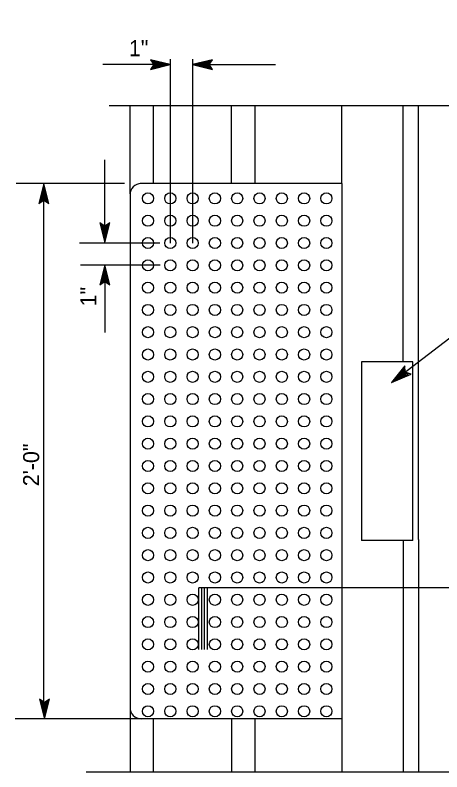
# Model space of a CAD drawing. Extents: x 6710407 to 6714861, y 1868090 to 1871317.
# Drawn here: x 6712493.6 to 6712653, y 1869454.7 to 1869737.5 of the extents above; entities that cross this region are included whole.
import ezdxf

# ---------------------------------------------------------------- set-up
doc = ezdxf.new("R2010")
doc.units = 0
for name, color, linetype in [('G-MARK', 7, 'Continuous'), ('G-TEXT', 7, 'Continuous'), ('Nongeo Data(60)', 7, 'Continuous')]:
    doc.layers.add(name, color=color, linetype=linetype)

msp = doc.modelspace()

# ---------------------------------------------------------------- linework, layer by layer
at = {"layer": 'G-MARK'}
for p, q in [((6712634.16, 1869600.18), (6712812.33, 1869737.52)), ((6712551.55, 1869652.35), (6712551.55, 1869721.02)), ((6712559.89, 1869652.35), (6712559.89, 1869721.02)), ((6712551.49, 1869719.01), (6712526.31, 1869719.01)), ((6712559.82, 1869719.01), (6712590.83, 1869719.01)), ((6712662.99, 1869703.6), (6712528.65, 1869703.6)), ((6712527.08, 1869652.44), (6712527.08, 1869683.45)), ((6712534.39, 1869674.55), (6712493.89, 1869674.55)), ((6712504.23, 1869479.61), (6712504.23, 1869674.55)), ((6712547.67, 1869652.35), (6712517.54, 1869652.35)), ((6712547.77, 1869644.02), (6712517.94, 1869644.02)), ((6712527.08, 1869644.11), (6712527.08, 1869618.94)), ((6712578.2, 1869474.55), (6712493.56, 1869474.55)), ((6712520.13, 1869454.7), (6712662.61, 1869454.7))]:
    msp.add_line(p, q, dxfattribs=at)
at = {"layer": 'G-TEXT'}
for points in [[(6712551.49, 1869719.01), (6712544.08, 1869720.86), (6712545.31, 1869719.01), (6712544.08, 1869717.15), (6712551.49, 1869719.01)], [(6712551.49, 1869719.01), (6712544.08, 1869720.86), (6712545.31, 1869719.01), (6712544.08, 1869717.15), (6712551.49, 1869719.01)], [(6712550.17, 1869719.01), (6712544.8, 1869720.35), (6712545.7, 1869719.01), (6712544.8, 1869717.66), (6712550.17, 1869719.01)], [(6712550.17, 1869719.01), (6712544.8, 1869720.35), (6712545.7, 1869719.01), (6712544.8, 1869717.66), (6712550.17, 1869719.01)], [(6712549.07, 1869719.01), (6712545.41, 1869719.93), (6712546.02, 1869719.01), (6712545.41, 1869718.09), (6712549.07, 1869719.01)], [(6712549.07, 1869719.01), (6712545.41, 1869719.93), (6712546.02, 1869719.01), (6712545.41, 1869718.09), (6712549.07, 1869719.01)], [(6712559.82, 1869719.01), (6712567.23, 1869717.15), (6712566, 1869719.01), (6712567.23, 1869720.86), (6712559.82, 1869719.01)], [(6712561.14, 1869719.01), (6712566.51, 1869717.66), (6712565.61, 1869719.01), (6712566.51, 1869720.35), (6712561.14, 1869719.01)], [(6712562.24, 1869719.01), (6712565.9, 1869718.09), (6712565.29, 1869719.01), (6712565.9, 1869719.93), (6712562.24, 1869719.01)], [(6712548.16, 1869719.01), (6712545.91, 1869719.58), (6712546.28, 1869719.01), (6712545.91, 1869718.44), (6712548.16, 1869719.01)], [(6712548.16, 1869719.01), (6712545.91, 1869719.58), (6712546.28, 1869719.01), (6712545.91, 1869718.44), (6712548.16, 1869719.01)], [(6712548.1, 1869718.78), (6712546.44, 1869719.19), (6712546.57, 1869719.01), (6712546.44, 1869718.82), (6712548.1, 1869719.24)], [(6712548.1, 1869718.78), (6712546.44, 1869719.19), (6712546.57, 1869719.01), (6712546.44, 1869718.82), (6712548.1, 1869719.24)], [(6712563.15, 1869719.01), (6712565.4, 1869718.44), (6712565.03, 1869719.01), (6712565.4, 1869719.58), (6712563.15, 1869719.01)], [(6712563.21, 1869719.24), (6712564.87, 1869718.82), (6712564.74, 1869719.01), (6712564.87, 1869719.19), (6712563.21, 1869718.78)], [(6712504.3, 1869674.55), (6712502.44, 1869667.15), (6712504.3, 1869668.38), (6712506.15, 1869667.15), (6712504.3, 1869674.55)], [(6712504.3, 1869674.55), (6712502.44, 1869667.15), (6712504.3, 1869668.38), (6712506.15, 1869667.15), (6712504.3, 1869674.55)], [(6712504.3, 1869673.24), (6712502.95, 1869667.87), (6712504.3, 1869668.76), (6712505.64, 1869667.87), (6712504.3, 1869673.24)], [(6712504.3, 1869673.24), (6712502.95, 1869667.87), (6712504.3, 1869668.76), (6712505.64, 1869667.87), (6712504.3, 1869673.24)], [(6712504.3, 1869672.14), (6712503.38, 1869668.48), (6712504.3, 1869669.09), (6712505.22, 1869668.48), (6712504.3, 1869672.14)], [(6712504.3, 1869672.14), (6712503.38, 1869668.48), (6712504.3, 1869669.09), (6712505.22, 1869668.48), (6712504.3, 1869672.14)], [(6712504.3, 1869671.23), (6712503.73, 1869668.98), (6712504.3, 1869669.35), (6712504.87, 1869668.98), (6712504.3, 1869671.23)], [(6712504.3, 1869671.23), (6712503.73, 1869668.98), (6712504.3, 1869669.35), (6712504.87, 1869668.98), (6712504.3, 1869671.23)], [(6712504.53, 1869671.17), (6712504.11, 1869669.51), (6712504.3, 1869669.63), (6712504.49, 1869669.51), (6712504.07, 1869671.17)], [(6712504.53, 1869671.17), (6712504.11, 1869669.51), (6712504.3, 1869669.63), (6712504.49, 1869669.51), (6712504.07, 1869671.17)], [(6712527.08, 1869652.44), (6712528.94, 1869659.85), (6712527.08, 1869658.62), (6712525.23, 1869659.85), (6712527.08, 1869652.44)], [(6712527.08, 1869653.76), (6712528.43, 1869659.13), (6712527.08, 1869658.23), (6712525.74, 1869659.13), (6712527.08, 1869653.76)], [(6712527.08, 1869654.86), (6712528, 1869658.52), (6712527.08, 1869657.91), (6712526.16, 1869658.52), (6712527.08, 1869654.86)], [(6712527.08, 1869655.77), (6712527.65, 1869658.02), (6712527.08, 1869657.65), (6712526.51, 1869658.02), (6712527.08, 1869655.77)], [(6712526.85, 1869655.83), (6712527.27, 1869657.49), (6712527.08, 1869657.37), (6712526.9, 1869657.49), (6712527.31, 1869655.83)], [(6712527.08, 1869644.11), (6712525.23, 1869636.7), (6712527.08, 1869637.93), (6712528.94, 1869636.7), (6712527.08, 1869644.11)], [(6712527.08, 1869644.11), (6712525.23, 1869636.7), (6712527.08, 1869637.93), (6712528.94, 1869636.7), (6712527.08, 1869644.11)], [(6712527.08, 1869642.8), (6712525.74, 1869637.43), (6712527.08, 1869638.32), (6712528.43, 1869637.43), (6712527.08, 1869642.8)], [(6712527.08, 1869642.8), (6712525.74, 1869637.43), (6712527.08, 1869638.32), (6712528.43, 1869637.43), (6712527.08, 1869642.8)], [(6712527.08, 1869641.69), (6712526.16, 1869638.04), (6712527.08, 1869638.65), (6712528, 1869638.04), (6712527.08, 1869641.69)], [(6712527.08, 1869641.69), (6712526.16, 1869638.04), (6712527.08, 1869638.65), (6712528, 1869638.04), (6712527.08, 1869641.69)], [(6712527.08, 1869640.78), (6712526.51, 1869638.53), (6712527.08, 1869638.9), (6712527.65, 1869638.53), (6712527.08, 1869640.78)], [(6712527.08, 1869640.78), (6712526.51, 1869638.53), (6712527.08, 1869638.9), (6712527.65, 1869638.53), (6712527.08, 1869640.78)], [(6712527.31, 1869640.73), (6712526.9, 1869639.07), (6712527.08, 1869639.19), (6712527.27, 1869639.07), (6712526.85, 1869640.73)], [(6712527.31, 1869640.73), (6712526.9, 1869639.07), (6712527.08, 1869639.19), (6712527.27, 1869639.07), (6712526.85, 1869640.73)], [(6712634.16, 1869600.18), (6712641.45, 1869603.36), (6712639.26, 1869604.11), (6712639.09, 1869606.42), (6712634.16, 1869600.18)], [(6712634.16, 1869600.18), (6712641.45, 1869603.36), (6712639.26, 1869604.11), (6712639.09, 1869606.42), (6712634.16, 1869600.18)], [(6712635.24, 1869601.02), (6712640.53, 1869603.33), (6712638.94, 1869603.87), (6712638.82, 1869605.54), (6712635.24, 1869601.02)], [(6712635.24, 1869601.02), (6712640.53, 1869603.33), (6712638.94, 1869603.87), (6712638.82, 1869605.54), (6712635.24, 1869601.02)], [(6712636.15, 1869601.72), (6712639.76, 1869603.29), (6712638.67, 1869603.66), (6712638.59, 1869604.81), (6712636.15, 1869601.72)], [(6712636.15, 1869601.72), (6712639.76, 1869603.29), (6712638.67, 1869603.66), (6712638.59, 1869604.81), (6712636.15, 1869601.72)], [(6712636.9, 1869602.3), (6712639.12, 1869603.26), (6712638.45, 1869603.49), (6712638.4, 1869604.2), (6712636.9, 1869602.3)], [(6712636.9, 1869602.3), (6712639.12, 1869603.26), (6712638.45, 1869603.49), (6712638.4, 1869604.2), (6712636.9, 1869602.3)], [(6712636.81, 1869602.53), (6712638.44, 1869603.24), (6712638.22, 1869603.31), (6712638.2, 1869603.55), (6712637.1, 1869602.15)], [(6712636.81, 1869602.53), (6712638.44, 1869603.24), (6712638.22, 1869603.31), (6712638.2, 1869603.55), (6712637.1, 1869602.15)], [(6712504.51, 1869474.49), (6712506.37, 1869481.9), (6712504.51, 1869480.67), (6712502.66, 1869481.9), (6712504.51, 1869474.49)], [(6712504.51, 1869475.81), (6712505.86, 1869481.18), (6712504.51, 1869480.28), (6712503.17, 1869481.18), (6712504.51, 1869475.81)], [(6712504.51, 1869476.91), (6712505.43, 1869480.57), (6712504.51, 1869479.96), (6712503.59, 1869480.57), (6712504.51, 1869476.91)], [(6712504.51, 1869477.82), (6712505.08, 1869480.07), (6712504.51, 1869479.7), (6712503.94, 1869480.07), (6712504.51, 1869477.82)], [(6712504.28, 1869477.88), (6712504.7, 1869479.54), (6712504.51, 1869479.42), (6712504.32, 1869479.54), (6712504.74, 1869477.88)]]:
    msp.add_lwpolyline(points, dxfattribs=at)
at = {"layer": 'Nongeo Data(60)'}
for p, q in [((6712536.48, 1869670.68), (6712536.48, 1869703.6)), ((6712545.3, 1869674.55), (6712545.3, 1869703.6)), ((6712574.41, 1869674.55), (6712574.41, 1869703.6)), ((6712583.23, 1869674.55), (6712583.23, 1869703.6)), ((6712615.65, 1869674.55), (6712615.65, 1869703.6)), ((6712638.51, 1869607.89), (6712638.51, 1869703.6)), ((6712644.18, 1869541.57), (6712644.18, 1869703.6)), ((6712615.65, 1869674.55), (6712540.27, 1869674.55)), ((6712615.65, 1869674.55), (6712615.65, 1869454.7)), ((6712536.48, 1869670.68), (6712536.48, 1869478.55)), ((6712622.92, 1869607.89), (6712622.92, 1869541.22)), ((6712642.15, 1869607.89), (6712622.92, 1869607.89)), ((6712642.15, 1869541.22), (6712642.15, 1869607.89)), ((6712644.18, 1869541.57), (6712644.18, 1869454.7)), ((6712642.15, 1869541.22), (6712622.92, 1869541.22)), ((6712638.51, 1869541.22), (6712638.51, 1869454.7)), ((6712792.35, 1869523.51), (6712562.23, 1869523.51)), ((6712562.23, 1869500.43), (6712562.23, 1869523.51)), ((6712563.28, 1869500.43), (6712563.28, 1869523.37)), ((6712564.34, 1869500.43), (6712564.34, 1869523.37)), ((6712565.4, 1869500.43), (6712565.4, 1869523.37)), ((6712536.48, 1869478.55), (6712536.48, 1869454.7)), ((6712615.65, 1869474.55), (6712540.65, 1869474.55)), ((6712545.3, 1869454.7), (6712545.3, 1869474.55)), ((6712574.41, 1869474.55), (6712574.41, 1869454.7)), ((6712583.23, 1869454.7), (6712583.23, 1869474.55))]:
    msp.add_line(p, q, dxfattribs=at)
for centre in [(6712543.17, 1869669.02), (6712551.5, 1869669.02), (6712559.84, 1869669.02), (6712568.17, 1869669.02), (6712576.5, 1869669.02), (6712584.84, 1869669.02), (6712593.17, 1869669.02), (6712601.5, 1869669.02), (6712609.84, 1869669.02), (6712543.17, 1869660.68), (6712551.5, 1869660.68), (6712559.84, 1869660.68), (6712568.17, 1869660.68), (6712576.5, 1869660.68), (6712584.84, 1869660.68), (6712593.17, 1869660.68), (6712601.5, 1869660.68), (6712609.84, 1869660.68), (6712543.17, 1869652.35), (6712551.5, 1869652.35), (6712559.84, 1869652.35), (6712568.17, 1869652.35), (6712576.5, 1869652.35), (6712584.84, 1869652.35), (6712593.17, 1869652.35), (6712601.5, 1869652.35), (6712609.84, 1869652.35), (6712543.17, 1869644.02), (6712551.5, 1869644.02), (6712559.84, 1869644.02), (6712568.17, 1869644.02), (6712576.5, 1869644.02), (6712584.84, 1869644.02), (6712593.17, 1869644.02), (6712601.5, 1869644.02), (6712609.84, 1869644.02), (6712543.17, 1869635.68), (6712551.5, 1869635.68), (6712559.84, 1869635.68), (6712568.17, 1869635.68), (6712576.5, 1869635.68), (6712584.84, 1869635.68), (6712593.17, 1869635.68), (6712601.5, 1869635.68), (6712609.84, 1869635.68), (6712543.17, 1869627.35), (6712551.5, 1869627.35), (6712559.84, 1869627.35), (6712568.17, 1869627.35), (6712576.5, 1869627.35), (6712584.84, 1869627.35), (6712593.17, 1869627.35), (6712601.5, 1869627.35), (6712609.84, 1869627.35), (6712543.17, 1869619.02), (6712551.5, 1869619.02), (6712559.84, 1869619.02), (6712568.17, 1869619.02), (6712576.5, 1869619.02), (6712584.84, 1869619.02), (6712593.17, 1869619.02), (6712601.5, 1869619.02), (6712609.84, 1869619.02), (6712543.17, 1869610.68), (6712551.5, 1869610.68), (6712559.84, 1869610.68), (6712568.17, 1869610.68), (6712576.5, 1869610.68), (6712584.84, 1869610.68), (6712593.17, 1869610.68), (6712601.5, 1869610.68), (6712609.84, 1869610.68), (6712543.17, 1869602.35), (6712551.5, 1869602.35), (6712559.84, 1869602.35), (6712568.17, 1869602.35), (6712576.5, 1869602.35), (6712584.84, 1869602.35), (6712593.17, 1869602.35), (6712601.5, 1869602.35), (6712609.84, 1869602.35), (6712543.17, 1869594.02), (6712551.5, 1869594.02), (6712559.84, 1869594.02), (6712568.17, 1869594.02), (6712576.5, 1869594.02), (6712584.84, 1869594.02), (6712593.17, 1869594.02), (6712601.5, 1869594.02), (6712609.84, 1869594.02), (6712543.17, 1869585.68), (6712551.5, 1869585.68), (6712559.84, 1869585.68), (6712568.17, 1869585.68), (6712576.5, 1869585.68), (6712584.84, 1869585.68), (6712593.17, 1869585.68), (6712601.5, 1869585.68), (6712609.84, 1869585.68), (6712543.17, 1869577.35), (6712551.5, 1869577.35), (6712559.84, 1869577.35), (6712568.17, 1869577.35), (6712576.5, 1869577.35), (6712584.84, 1869577.35), (6712593.17, 1869577.35), (6712601.5, 1869577.35), (6712609.84, 1869577.35), (6712543.17, 1869569.02), (6712551.5, 1869569.02), (6712559.84, 1869569.02), (6712568.17, 1869569.02), (6712576.5, 1869569.02), (6712584.84, 1869569.02), (6712593.17, 1869569.02), (6712601.5, 1869569.02), (6712609.84, 1869569.02), (6712543.17, 1869560.68), (6712551.5, 1869560.68), (6712559.84, 1869560.68), (6712568.17, 1869560.68), (6712576.5, 1869560.68), (6712584.84, 1869560.68), (6712593.17, 1869560.68), (6712601.5, 1869560.68), (6712609.84, 1869560.68), (6712543.17, 1869552.35), (6712551.5, 1869552.35), (6712559.84, 1869552.35), (6712568.17, 1869552.35), (6712576.5, 1869552.35), (6712584.84, 1869552.35), (6712593.17, 1869552.35), (6712601.5, 1869552.35), (6712609.84, 1869552.35), (6712543.17, 1869544.02), (6712551.5, 1869544.02), (6712559.84, 1869544.02), (6712568.17, 1869544.02), (6712576.5, 1869544.02), (6712584.84, 1869544.02), (6712593.17, 1869544.02), (6712601.5, 1869544.02), (6712609.84, 1869544.02), (6712543.17, 1869535.68), (6712551.5, 1869535.68), (6712559.84, 1869535.68), (6712568.17, 1869535.68), (6712576.5, 1869535.68), (6712584.84, 1869535.68), (6712593.17, 1869535.68), (6712601.5, 1869535.68), (6712609.84, 1869535.68), (6712543.17, 1869527.35), (6712551.5, 1869527.35), (6712559.84, 1869527.35), (6712568.17, 1869527.35), (6712576.5, 1869527.35), (6712584.84, 1869527.35), (6712593.17, 1869527.35), (6712601.5, 1869527.35), (6712609.84, 1869527.35), (6712543.17, 1869519.02), (6712551.5, 1869519.02), (6712559.84, 1869519.02), (6712568.17, 1869519.02), (6712576.5, 1869519.02), (6712584.84, 1869519.02), (6712593.17, 1869519.02), (6712601.5, 1869519.02), (6712609.84, 1869519.02), (6712543.17, 1869510.68), (6712551.5, 1869510.68), (6712559.84, 1869510.68), (6712568.17, 1869510.68), (6712576.5, 1869510.68), (6712584.84, 1869510.68), (6712593.17, 1869510.68), (6712601.5, 1869510.68), (6712609.84, 1869510.68), (6712543.17, 1869502.35), (6712551.5, 1869502.35), (6712559.84, 1869502.35), (6712568.17, 1869502.35), (6712576.5, 1869502.35), (6712584.84, 1869502.35), (6712593.17, 1869502.35), (6712601.5, 1869502.35), (6712609.84, 1869502.35), (6712543.17, 1869494.02), (6712551.5, 1869494.02), (6712559.84, 1869494.02), (6712568.17, 1869494.02), (6712576.5, 1869494.02), (6712584.84, 1869494.02), (6712593.17, 1869494.02), (6712601.5, 1869494.02), (6712609.84, 1869494.02), (6712543.17, 1869485.68), (6712551.5, 1869485.68), (6712559.84, 1869485.68), (6712568.17, 1869485.68), (6712576.5, 1869485.68), (6712584.84, 1869485.68), (6712593.17, 1869485.68), (6712601.5, 1869485.68), (6712609.84, 1869485.68), (6712543.17, 1869477.35), (6712551.5, 1869477.35), (6712559.84, 1869477.35), (6712568.17, 1869477.35), (6712576.5, 1869477.35), (6712584.84, 1869477.35), (6712593.17, 1869477.35), (6712601.5, 1869477.35), (6712609.84, 1869477.35)]:
    msp.add_circle(centre, 2.08, dxfattribs=at)
for centre, start, end in [((6712540.65, 1869670.39), 90, 180), ((6712540.65, 1869478.72), 180, 270)]:
    msp.add_arc(centre, 4.17, start, end, dxfattribs=at)

# ---------------------------------------------------------------- texts
msp.add_text('1"', height=6, dxfattribs=at).set_placement((6712536.04, 1869722.17))
for s, p in [('1"', (6712523.91, 1869628.66)), ('2\'-0"', (6712502.53, 1869561.44))]:
    msp.add_text(s, height=6, rotation=90, dxfattribs=at).set_placement(p)

doc.saveas('drawing.dxf')
